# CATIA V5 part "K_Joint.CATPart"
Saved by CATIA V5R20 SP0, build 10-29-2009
Part number: Joint
Property "Diamètre joint": 20 mm
Bounding box of the stored display mesh (mm): x -23.075 to 23.075, y -20.451 to 20.451, z -85 to 0
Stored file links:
  C:\Users\thinkmotion1\Desktop\Khaled_IAO_Pack2\Problemes\IAO_2010_1405_jpalas\IAO_PALAS\Khaled_Palas\K_Joint.CATPart
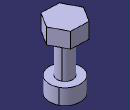
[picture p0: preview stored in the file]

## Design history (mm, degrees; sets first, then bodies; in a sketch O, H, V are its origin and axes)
Body1 (main body)
  Sketch1 on zx-plane, origin (0, 0, 0), H (0, 0, 1), V (1, 0, 0)
    line L1 (0, 0) -> (0, 10)
    line L2 (0, 10) -> (-65, 10)
    line L3 (-65, 10) -> (-65, 20)
    line L4 (-65, 20) -> (-85, 20)
    line L5 (-85, 20) -> (-85, 0)
    point P5 (-85, 0)
    line L6 (-85, 0) -> (0, 0)
    length L5 = 20
    distance L2 L6 = 10
    length L4 = 20
    length L6 = 85
    vertical: L1 V, L3 V, L5 V
    horizontal: L2 H, L4 H, L6 H
    coincidence: P5 H
  Shaft1: profile Sketch1, axis Sketch1.L6, angle 360
  Sketch2 on face of Shaft1 from Sketch1.L1, origin (0, 0, 0), H (1, 0, 0), V (0, 1, 0)
    point P1 (-12.3462, -19.5168)
    point P2 (10.7289, -20.4505)
    point P3 (23.0751, -0.9337)
    point P4 (12.3462, 19.5168)
    point P5 (-10.7289, 20.4505)
    point P6 (-23.0751, 0.9337)
    point P7 (-0.8086, -19.9836)
    line L1 (-12.3462, -19.5168) -> (10.7289, -20.4505)
    line L2 (10.7289, -20.4505) -> (23.0751, -0.9337)
    line L3 (23.0751, -0.9337) -> (12.3462, 19.5168)
    line L4 (12.3462, 19.5168) -> (-10.7289, 20.4505)
    line L5 (-10.7289, 20.4505) -> (-23.0751, 0.9337)
    line L6 (-23.0751, 0.9337) -> (-12.3462, -19.5168)
    construction line L7 (0, 0) -> (-0.8086, -19.9836)
    construction circle A1 centre (0, 0) radius 23.094
    construction arc A2 centre (-10.7289, 20.4505) radius 23.094 from (12.3462, 19.5168) to (-23.0751, 0.9337) cw
    construction arc A3 centre (10.7289, -20.4505) radius 23.094 from (23.0751, -0.9337) to (-12.3462, -19.5168) ccw
    circle A4 centre (0, 0) radius 10
    point P8 (0, 0)
    distance L4 L1 = 40
    radius A4 = 10
    coincidence: A1 P1, A1 P2, A1 P3, A1 P4, A1 P5, A1 P6, A2 O, A3 O, P8 O
    midpoint: P7 L1
  Pad1: profile Sketch2, direction (0, 0, -1), length 20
